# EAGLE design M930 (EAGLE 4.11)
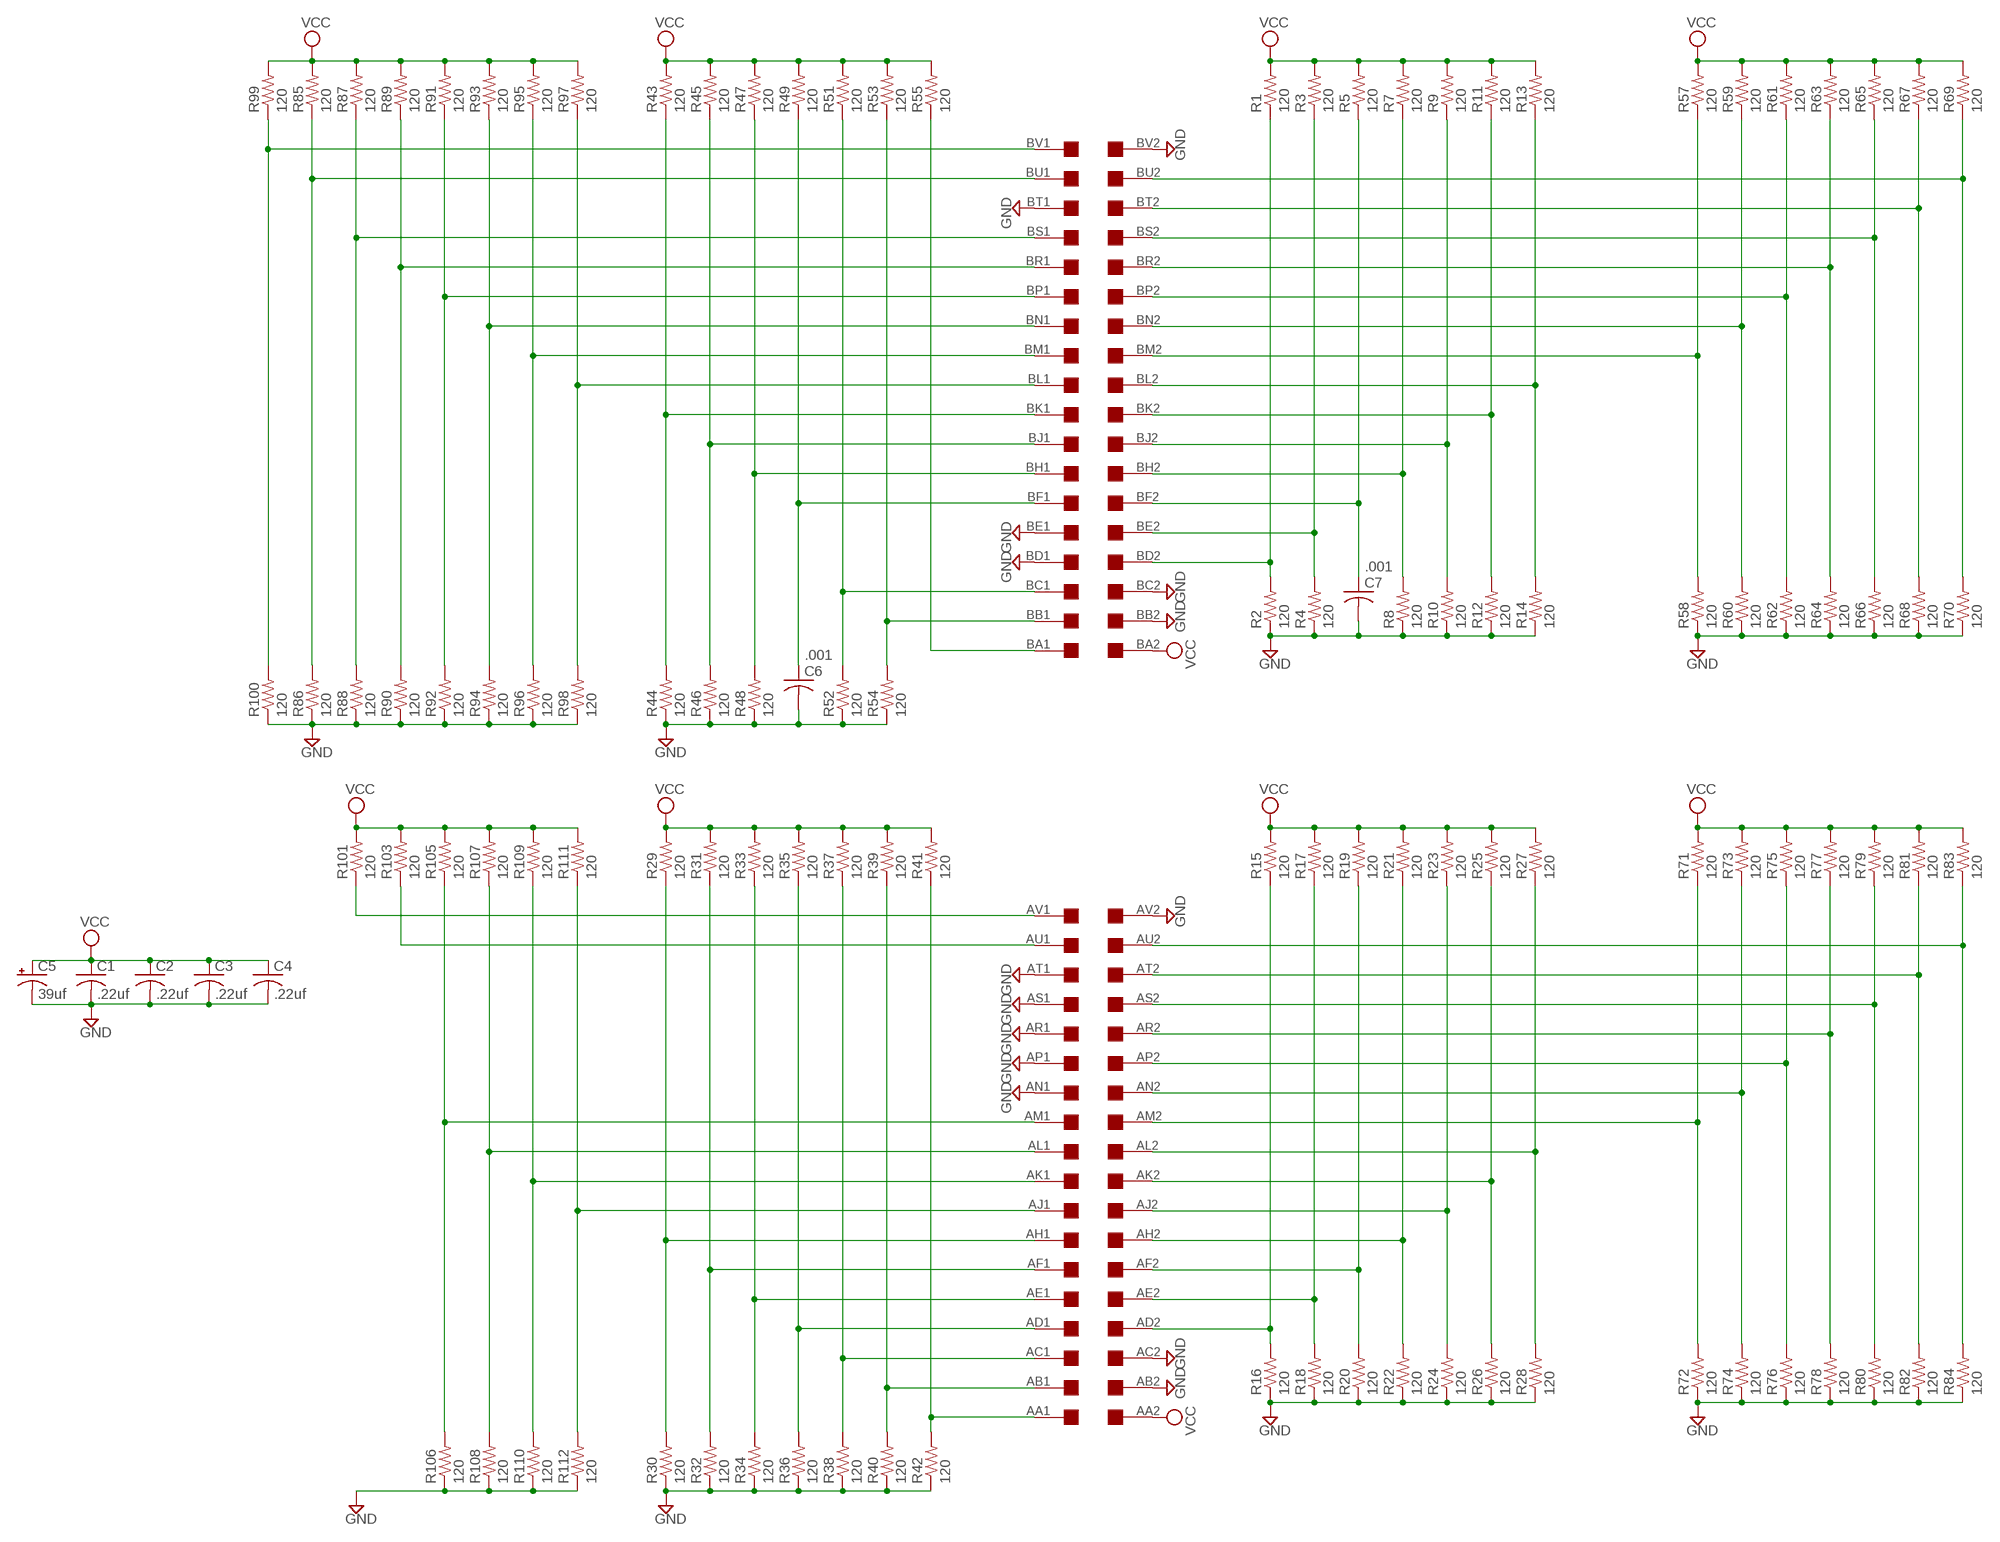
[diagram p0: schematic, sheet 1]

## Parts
C1  .22uf  C-US050-025X075  [C050-025X075]
C2  .22uf  C-US050-025X075  [C050-025X075]
C3  .22uf  C-US050-025X075  [C050-025X075]
C4  .22uf  C-US050-025X075  [C050-025X075]
C5  39uf  CPOL-USE15-5AXIAL  [E15-5]
C6  .001  C-US050-025X075  [C050-025X075]
C7  .001  C-US050-025X075  [C050-025X075]
R1  120  R-US_0207/10  [0207/10]
R2  120  R-US_0207/10  [0207/10]
R3  120  R-US_0207/10  [0207/10]
R4  120  R-US_0207/10  [0207/10]
R5  120  R-US_0207/10  [0207/10]
R7  120  R-US_0207/10  [0207/10]
R8  120  R-US_0207/10  [0207/10]
R9  120  R-US_0207/10  [0207/10]
R10  120  R-US_0207/10  [0207/10]
R11  120  R-US_0207/10  [0207/10]
R12  120  R-US_0207/10  [0207/10]
R13  120  R-US_0207/10  [0207/10]
R14  120  R-US_0207/10  [0207/10]
R15  120  R-US_0207/10  [0207/10]
R16  120  R-US_0207/10  [0207/10]
R17  120  R-US_0207/10  [0207/10]
R18  120  R-US_0207/10  [0207/10]
R19  120  R-US_0207/10  [0207/10]
R20  120  R-US_0207/10  [0207/10]
R21  120  R-US_0207/10  [0207/10]
R22  120  R-US_0207/10  [0207/10]
R23  120  R-US_0207/10  [0207/10]
R24  120  R-US_0207/10  [0207/10]
R25  120  R-US_0207/10  [0207/10]
R26  120  R-US_0207/10  [0207/10]
R27  120  R-US_0207/10  [0207/10]
R28  120  R-US_0207/10  [0207/10]
R29  120  R-US_0207/10  [0207/10]
R30  120  R-US_0207/10  [0207/10]
R31  120  R-US_0207/10  [0207/10]
R32  120  R-US_0207/10  [0207/10]
R33  120  R-US_0207/10  [0207/10]
R34  120  R-US_0207/10  [0207/10]
R35  120  R-US_0207/10  [0207/10]
R36  120  R-US_0207/10  [0207/10]
R37  120  R-US_0207/10  [0207/10]
R38  120  R-US_0207/10  [0207/10]
R39  120  R-US_0207/10  [0207/10]
R40  120  R-US_0207/10  [0207/10]
R41  120  R-US_0207/10  [0207/10]
R42  120  R-US_0207/10  [0207/10]
R43  120  R-US_0207/10  [0207/10]
R44  120  R-US_0207/10  [0207/10]
R45  120  R-US_0207/10  [0207/10]
R46  120  R-US_0207/10  [0207/10]
R47  120  R-US_0207/10  [0207/10]
R48  120  R-US_0207/10  [0207/10]
R49  120  R-US_0207/10  [0207/10]
R51  120  R-US_0207/10  [0207/10]
R52  120  R-US_0207/10  [0207/10]
R53  120  R-US_0207/10  [0207/10]
R54  120  R-US_0207/10  [0207/10]
R55  120  R-US_0207/10  [0207/10]
R57  120  R-US_0207/10  [0207/10]
R58  120  R-US_0207/10  [0207/10]
R59  120  R-US_0207/10  [0207/10]
R60  120  R-US_0207/10  [0207/10]
R61  120  R-US_0207/10  [0207/10]
R62  120  R-US_0207/10  [0207/10]
R63  120  R-US_0207/10  [0207/10]
R64  120  R-US_0207/10  [0207/10]
R65  120  R-US_0207/10  [0207/10]
R66  120  R-US_0207/10  [0207/10]
R67  120  R-US_0207/10  [0207/10]
R68  120  R-US_0207/10  [0207/10]
R69  120  R-US_0207/10  [0207/10]
R70  120  R-US_0207/10  [0207/10]
R71  120  R-US_0207/10  [0207/10]
R72  120  R-US_0207/10  [0207/10]
R73  120  R-US_0207/10  [0207/10]
R74  120  R-US_0207/10  [0207/10]
R75  120  R-US_0207/10  [0207/10]
R76  120  R-US_0207/10  [0207/10]
R77  120  R-US_0207/10  [0207/10]
R78  120  R-US_0207/10  [0207/10]
R79  120  R-US_0207/10  [0207/10]
R80  120  R-US_0207/10  [0207/10]
R81  120  R-US_0207/10  [0207/10]
R82  120  R-US_0207/10  [0207/10]
R83  120  R-US_0207/10  [0207/10]
R84  120  R-US_0207/10  [0207/10]
R85  120  R-US_0207/10  [0207/10]
R86  120  R-US_0207/10  [0207/10]
R87  120  R-US_0207/10  [0207/10]
R88  120  R-US_0207/10  [0207/10]
R89  120  R-US_0207/10  [0207/10]
R90  120  R-US_0207/10  [0207/10]
R91  120  R-US_0207/10  [0207/10]
R92  120  R-US_0207/10  [0207/10]
R93  120  R-US_0207/10  [0207/10]
R94  120  R-US_0207/10  [0207/10]
R95  120  R-US_0207/10  [0207/10]
R96  120  R-US_0207/10  [0207/10]
R97  120  R-US_0207/10  [0207/10]
R98  120  R-US_0207/10  [0207/10]
R99  120  R-US_0207/10  [0207/10]
R100  120  R-US_0207/10  [0207/10]
R101  120  R-US_0207/10  [0207/10]
R103  120  R-US_0207/10  [0207/10]
R105  120  R-US_0207/10  [0207/10]
R106  120  R-US_0207/10  [0207/10]
R107  120  R-US_0207/10  [0207/10]
R108  120  R-US_0207/10  [0207/10]
R109  120  R-US_0207/10  [0207/10]
R110  120  R-US_0207/10  [0207/10]
R111  120  R-US_0207/10  [0207/10]
R112  120  R-US_0207/10  [0207/10]
U$1  DOUBLE  [EDGE-CON4]

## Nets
AA1: R41.1 R42.2 U$1.AA1
AB1: R39.1 R40.2 U$1.AB1
AC1: R37.1 R38.2 U$1.AC1
AD1: R35.1 R36.2 U$1.AD1
AD2: R15.1 R16.2 U$1.AD2
AE1: R33.1 R34.2 U$1.AE1
AE2: R17.1 R18.2 U$1.AE2
AF1: R31.1 R32.2 U$1.AF1
AF2: R19.1 R20.2 U$1.AF2
AH1: R29.1 R30.2 U$1.AH1
AH2: R21.1 R22.2 U$1.AH2
AJ1: R111.1 R112.2 U$1.AJ1
AJ2: R23.1 R24.2 U$1.AJ2
AK1: R109.1 R110.2 U$1.AK1
AK2: R25.1 R26.2 U$1.AK2
AL1: R107.1 R108.2 U$1.AL1
AL2: R27.1 R28.2 U$1.AL2
AM1: R105.1 R106.2 U$1.AM1
AM2: R71.1 R72.2 U$1.AM2
AN2: R73.1 R74.2 U$1.AN2
AP2: R75.1 R76.2 U$1.AP2
AR2: R77.1 R78.2 U$1.AR2
AS2: R79.1 R80.2 U$1.AS2
AT2: R81.1 R82.2 U$1.AT2
AU1: R103.1 U$1.AU1
AU2: R83.1 R84.2 U$1.AU2
AV1: R101.1 U$1.AV1
BA1: R55.1 U$1.BA1
BB1: R53.1 R54.2 U$1.BB1
BC1: R51.1 R52.2 U$1.BC1
BD2: R1.1 R2.2 U$1.BD2
BE2: R3.1 R4.2 U$1.BE2
BF1: C6.1 R49.1 U$1.BF1
BF2: C7.1 R5.1 U$1.BF2
BH1: R47.1 R48.2 U$1.BH1
BH2: R7.1 R8.2 U$1.BH2
BJ1: R45.1 R46.2 U$1.BJ1
BJ2: R9.1 R10.2 U$1.BJ2
BK1: R43.1 R44.2 U$1.BK1
BK2: R11.1 R12.2 U$1.BK2
BL1: R97.1 R98.2 U$1.BL1
BL2: R13.1 R14.2 U$1.BL2
BM1: R95.1 R96.2 U$1.BM1
BM2: R57.1 R58.2 U$1.BM2
BN1: R93.1 R94.2 U$1.BN1
BN2: R59.1 R60.2 U$1.BN2
BP1: R91.1 R92.2 U$1.BP1
BP2: R61.1 R62.2 U$1.BP2
BR1: R89.1 R90.2 U$1.BR1
BR2: R63.1 R64.2 U$1.BR2
BS1: R87.1 R88.2 U$1.BS1
BS2: R65.1 R66.2 U$1.BS2
BT2: R67.1 R68.2 U$1.BT2
BU1: R85.1 R86.2 U$1.BU1
BU2: R69.1 R70.2 U$1.BU2
BV1: R99.1 R100.2 U$1.BV1
GND: C1.2 C2.2 C3.2 C4.2 C5.- C6.2 C7.2 R2.1 R4.1 R8.1 R10.1 R12.1 R14.1 R16.1 R18.1 R20.1 R22.1 R24.1 R26.1 R28.1 R30.1 R32.1 R34.1 R36.1 R38.1 R40.1 R42.1 R44.1 R46.1 R48.1 R52.1 R54.1 R58.1 R60.1 R62.1 R64.1 R66.1 R68.1 R70.1 R72.1 R74.1 R76.1 R78.1 R80.1 R82.1 R84.1 R86.1 R88.1 R90.1 R92.1 R94.1 R96.1 R98.1 R100.1 R106.1 R108.1 R110.1 R112.1 U$1.AB2 U$1.AC2 U$1.AN1 U$1.AP1 U$1.AR1 U$1.AS1 U$1.AT1 U$1.AV2 U$1.BB2 U$1.BC2 U$1.BD1 U$1.BE1 U$1.BT1 U$1.BV2
VCC: C1.1 C2.1 C3.1 C4.1 C5.+ R1.2 R3.2 R5.2 R7.2 R9.2 R11.2 R13.2 R15.2 R17.2 R19.2 R21.2 R23.2 R25.2 R27.2 R29.2 R31.2 R33.2 R35.2 R37.2 R39.2 R41.2 R43.2 R45.2 R47.2 R49.2 R51.2 R53.2 R55.2 R57.2 R59.2 R61.2 R63.2 R65.2 R67.2 R69.2 R71.2 R73.2 R75.2 R77.2 R79.2 R81.2 R83.2 R85.2 R87.2 R89.2 R91.2 R93.2 R95.2 R97.2 R99.2 R101.2 R103.2 R105.2 R107.2 R109.2 R111.2 U$1.AA2 U$1.BA2

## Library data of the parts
C1-C4 C6 C7 = rcl:C-US: CAPACITOR, American symbol
C5 = rcl:CPOL-US: POLARIZED CAPACITOR, American symbol
R1-R5 R7-R49 R51-R55 R57-R101 R103 R105-R112 = rcl:R-US_: RESISTOR, American symbol
U$1 = dec-con:DOUBLE: Double-Height DEC board

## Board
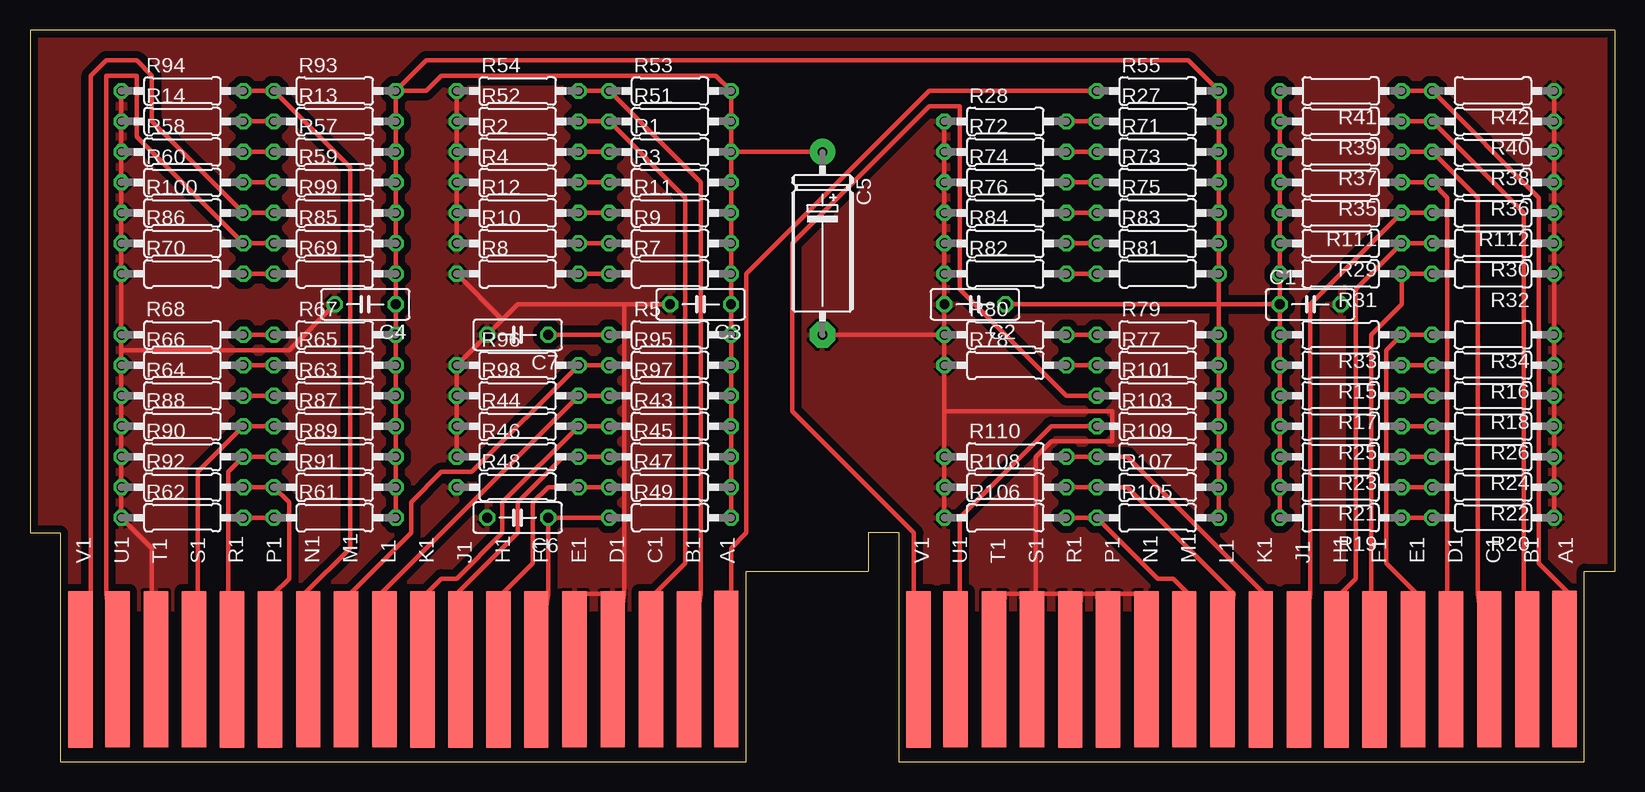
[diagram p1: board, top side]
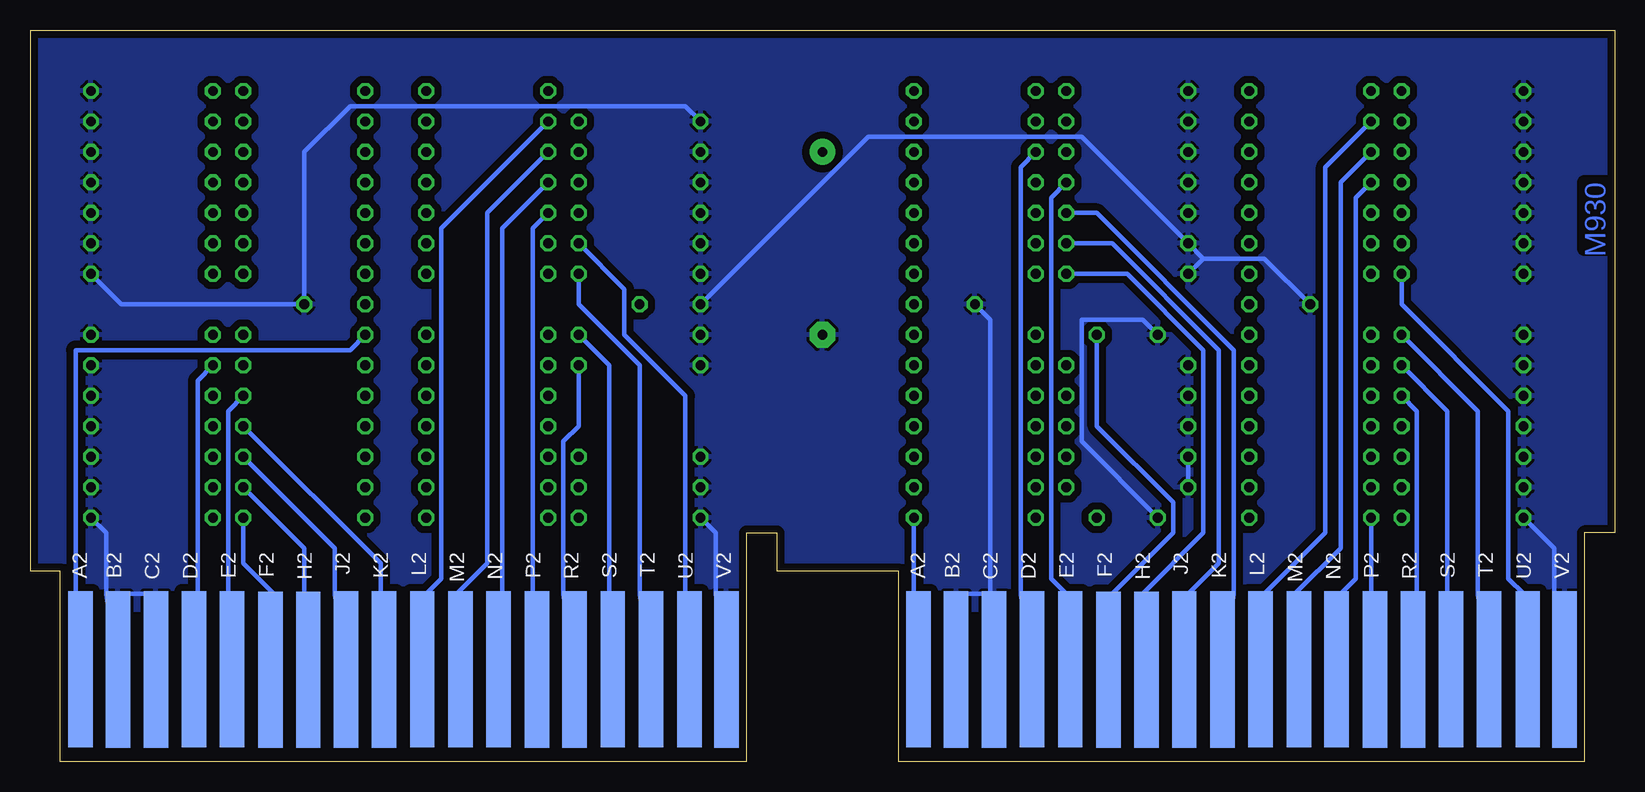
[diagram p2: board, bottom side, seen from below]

Size 132.08 x 60.96 mm. Coordinates in mm from the lower left corner, seen from the top.
Outline: 132.08,15.88 132.08,60.96 0,60.96 0,19.05
Copper layers (1*16): Top 0.035mm / dielectric 1.5mm / Bottom 0.035mm
Design rules "15mils": minimum track width 15mil, minimum drill 24mil, track to track 15mil, track to pad 10mil, pad to pad 10mil, via to via 10mil, smd to smd 10mil, copper to edge 25mil, drill to drill 10mil, minimum pad ring 10mil, minimum via ring 8mil, stop-mask expansion 0mil, vias tented up to drill 0mil, thermal gap 10mil

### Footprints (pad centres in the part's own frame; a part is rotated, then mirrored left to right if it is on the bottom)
C050-025X075 = drill 0.813 octagon: 1 -2.54,0; 2 2.54,0
E15-5 = drill 0.813 pad 2.159 round: + -7.62,0 | drill 0.813 pad 2.159 octagon: - 7.62,0
0207/10 = drill 0.813 octagon: 1 -5.08,0; 2 5.08,0
EDGE-CON4 = smd 13.017 x 2.032: AA1 7.709,4.207; AB1 7.684,7.312; AC1 7.684,10.474; AD1 7.684,13.665; AE1 7.693,16.84; AF1 7.668,20.041; AH1 7.668,23.19; AJ1 7.668,26.34; AK1 7.668,29.515; AL1 7.693,32.69; AM1 7.693,35.89; AN1 7.693,39.04; AP1 7.668,42.24; AR1 7.668,45.39; AS1 7.693,48.565; AT1 7.693,51.74; AU1 7.693,54.94; AV1 7.668,58.026; BA1 7.709,74.057; BB1 7.684,77.162; BC1 7.684,80.324; BD1 7.684,83.515; BE1 7.693,86.69; BF1 7.668,89.891; BH1 7.668,93.04; BJ1 7.668,96.19; BK1 7.668,99.365; BL1 7.693,102.54; BM1 7.693,105.74; BN1 7.693,108.89; BP1 7.668,112.09; BR1 7.668,115.24; BS1 7.693,118.415; BT1 7.693,121.59; BU1 7.693,124.79; BV1 7.668,127.876 | smd 13.017 x 2.032 bottom: AA2 7.69,4.207; AB2 7.668,7.328; AC2 7.668,10.49; AD2 7.693,13.665; AE2 7.693,16.84; AF2 7.642,20.041; AH2 7.642,23.19; AJ2 7.668,26.34; AK2 7.668,29.515; AL2 7.693,32.69; AM2 7.693,35.89; AN2 7.693,39.04; AP2 7.668,42.24; AR2 7.668,45.39; AS2 7.693,48.565; AT2 7.693,51.74; AU2 7.693,54.966; AV2 7.668,58.026; BA2 7.69,74.057; BB2 7.668,77.178; BC2 7.668,80.34; BD2 7.693,83.515; BE2 7.693,86.69; BF2 7.642,89.891; BH2 7.642,93.04; BJ2 7.668,96.19; BK2 7.668,99.365; BL2 7.693,102.54; BM2 7.693,105.74; BN2 7.693,108.89; BP2 7.668,112.09; BR2 7.668,115.24; BS2 7.693,118.415; BT2 7.693,121.59; BU2 7.693,124.816; BV2 7.668,127.876

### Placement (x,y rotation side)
C1  106.68,38.1 0 top
C2  78.74,38.1 180 top
C3  55.88,38.1 180 top
C4  27.94,38.1 180 top
C5  66.04,43.18 270 top
C6  40.64,20.32 180 top
C7  40.64,35.56 180 top
R1  53.34,50.8 0 top
R2  40.64,50.8 0 top
R3  53.34,48.26 0 top
R4  40.64,48.26 0 top
R5  53.34,35.56 0 top
R7  53.34,40.64 0 top
R8  40.64,40.64 0 top
R9  53.34,43.18 0 top
R10  40.64,43.18 0 top
R11  53.34,45.72 0 top
R12  40.64,45.72 0 top
R13  25.4,53.34 0 top
R14  12.7,53.34 0 top
R15  109.22,33.02 180 top
R16  121.92,33.02 180 top
R17  109.22,30.48 180 top
R18  121.92,30.48 180 top
R19  109.22,20.32 180 top
R20  121.92,20.32 180 top
R21  109.22,22.86 180 top
R22  121.92,22.86 180 top
R23  109.22,25.4 180 top
R24  121.92,25.4 180 top
R25  109.22,27.94 180 top
R26  121.92,27.94 180 top
R27  93.98,53.34 0 top
R28  81.28,53.34 0 top
R29  109.22,43.18 180 top
R30  121.92,43.18 180 top
R31  109.22,40.64 180 top
R32  121.92,40.64 180 top
R33  109.22,35.56 180 top
R34  121.92,35.56 180 top
R35  109.22,48.26 180 top
R36  121.92,48.26 180 top
R37  109.22,50.8 180 top
R38  121.92,50.8 180 top
R39  109.22,53.34 180 top
R40  121.92,53.34 180 top
R41  109.22,55.88 180 top
R42  121.92,55.88 180 top
R43  53.34,27.94 0 top
R44  40.64,27.94 0 top
R45  53.34,25.4 0 top
R46  40.64,25.4 0 top
R47  53.34,22.86 0 top
R48  40.64,22.86 0 top
R49  53.34,20.32 0 top
R51  53.34,53.34 0 top
R52  40.64,53.34 0 top
R53  53.34,55.88 0 top
R54  40.64,55.88 0 top
R55  93.98,55.88 0 top
R57  25.4,50.8 0 top
R58  12.7,50.8 0 top
R59  25.4,48.26 0 top
R60  12.7,48.26 0 top
R61  25.4,20.32 0 top
R62  12.7,20.32 0 top
R63  25.4,30.48 0 top
R64  12.7,30.48 0 top
R65  25.4,33.02 0 top
R66  12.7,33.02 0 top
R67  25.4,35.56 0 top
R68  12.7,35.56 0 top
R69  25.4,40.64 0 top
R70  12.7,40.64 0 top
R71  93.98,50.8 0 top
R72  81.28,50.8 0 top
R73  93.98,48.26 0 top
R74  81.28,48.26 0 top
R75  93.98,45.72 0 top
R76  81.28,45.72 0 top
R77  93.98,33.02 0 top
R78  81.28,33.02 0 top
R79  93.98,35.56 0 top
R80  81.28,35.56 0 top
R81  93.98,40.64 0 top
R82  81.28,40.64 0 top
R83  93.98,43.18 0 top
R84  81.28,43.18 0 top
R85  25.4,43.18 0 top
R86  12.7,43.18 0 top
R87  25.4,27.94 0 top
R88  12.7,27.94 0 top
R89  25.4,25.4 0 top
R90  12.7,25.4 0 top
R91  25.4,22.86 0 top
R92  12.7,22.86 0 top
R93  25.4,55.88 0 top
R94  12.7,55.88 0 top
R95  53.34,33.02 0 top
R96  40.64,33.02 0 top
R97  53.34,30.48 0 top
R98  40.64,30.48 0 top
R99  25.4,45.72 0 top
R100  12.7,45.72 0 top
R101  93.98,30.48 0 top
R103  93.98,27.94 0 top
R105  93.98,20.32 0 top
R106  81.28,20.32 0 top
R107  93.98,22.86 0 top
R108  81.28,22.86 0 top
R109  93.98,25.4 0 top
R110  81.28,25.4 0 top
R111  109.22,45.72 180 top
R112  121.92,45.72 180 top
U$1  132.08,0 90 top

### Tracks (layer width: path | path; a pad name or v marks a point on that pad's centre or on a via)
AA1
  Top 0.381: R41.1 R42.2 125.73,46.99 125.73,16.51 128.27,13.97 U$1.AA1
AB1
  Top 0.381: R39.1 R40.2 124.46,45.72 124.46,13.97 U$1.AB1
AC1
  Top 0.381: R37.1 R38.2 120.65,46.99 120.65,13.97 U$1.AC1
AD1
  Top 0.381: R35.1 R36.2 118.11,46.99 118.11,13.97 U$1.AD1
AD2
  Top 0.381: R16.2 R15.1
  Bottom 0.381: R16.2 118.11,31.75 118.11,13.97 U$1.AD2
AE1
  Top 0.381: R34.2 R33.1 113.03,34.29 113.03,16.51 115.57,13.97 U$1.AE1
AE2
  Top 0.381: R17.1 R18.2
  Bottom 0.381: R17.1 115.57,29.21 115.57,13.97 U$1.AE2
AF1
  Top 0.381: R32.2 R31.1 114.3,38.1 111.76,35.56 111.76,13.97 U$1.AF1
AF2
  Top 0.381: R19.1 R20.2
  Bottom 0.381: R19.1 114.3,16.51 111.76,13.97 U$1.AF2
AH1
  Top 0.381: R30.2 R29.1 110.49,39.37 110.49,15.24 109.22,13.97 U$1.AH1
AH2
  Top 0.381: R21.1 R22.2
  Bottom 0.381: R21.1 109.22,17.78 109.22,13.97 U$1.AH2
AJ1
  Top 0.381: R112.2 R111.1 106.68,38.1 106.68,13.97 U$1.AJ1
AJ2
  Top 0.381: R23.1 R24.2
  Bottom 0.381: R23.1 106.68,17.78 106.68,13.97 U$1.AJ2
AK1
  Top 0.381: R110.2 R109.1 91.44,25.4 102.87,13.97 U$1.AK1
AK2
  Top 0.381: R25.1 R26.2
  Bottom 0.381: R25.1 102.87,16.51 102.87,13.97 U$1.AK2
AL1
  Top 0.381: R108.2 R107.1 91.44,22.86 100.33,13.97 U$1.AL1
AL2
  Top 0.381: R27.1 R28.2
  Bottom 0.381: R27.1 97.79,44.45 97.79,15.24 99.06,13.97 U$1.AL2
AM1
  Top 0.381: R106.2 R105.1 93.98,15.24 95.25,15.24 96.52,13.97 U$1.AM1
AM2
  Top 0.381: R71.1 R72.2
  Bottom 0.381: R71.1 93.98,45.72 93.98,16.51 96.52,13.97 U$1.AM2
AN2
  Top 0.381: R73.1 R74.2
  Bottom 0.381: R73.1 92.71,44.45 92.71,13.97 U$1.AN2
AP2
  Top 0.381: R75.1 R76.2
  Bottom 0.381: R75.1 90.17,44.45 90.17,13.97 U$1.AP2
AR2
  Top 0.381: R78.2 R77.1
  Bottom 0.381: R78.2 86.36,27.94 87.63,26.67 87.63,13.97 U$1.AR2
AS2
  Top 0.381: R80.2 R79.1
  Bottom 0.381: R80.2 83.82,33.02 83.82,13.97 U$1.AS2
AT2
  Top 0.381: R82.2 R81.1
  Bottom 0.381: R82.2 86.36,38.1 81.28,33.02 81.28,13.97 U$1.AT2
AU1
  Top 0.381: R103.1 85.09,27.94 77.47,20.32 77.47,13.97 U$1.AU1
AU2
  Top 0.381: R84.2 R83.1
  Bottom 0.381: R84.2 82.55,39.37 82.55,35.56 77.47,30.48 77.47,13.97 U$1.AU2
AV1
  Top 0.381: R101.1 86.36,30.48 77.47,39.37 77.47,54.61 74.93,54.61 63.5,43.18 63.5,29.21 73.66,19.05 73.66,13.97 U$1.AV1
BA1
  Top 0.381: R55.1 74.93,55.88 59.69,40.64 59.69,19.05 58.42,17.78 58.42,13.97 U$1.BA1
BB1
  Top 0.381: R54.2 R53.1 55.88,48.26 55.88,13.97 U$1.BB1
BC1
  Top 0.381: R52.2 R51.1 54.61,46.99 54.61,16.51 52.07,13.97 U$1.BC1
BD2
  Top 0.381: R1.1 R2.2
  Bottom 0.381: R1.1 49.53,49.53 49.53,13.97 U$1.BD2
BE2
  Top 0.381: R4.2 R3.1
  Bottom 0.381: R4.2 46.99,46.99 46.99,15.24 45.72,13.97 U$1.BE2
BF1
  Top 0.381: R49.1 C6.1 43.18,13.97 U$1.BF1
BF2
  Top 0.381: C7.1 R5.1
  Bottom 0.381: C7.1 43.18,27.94 36.83,21.59 36.83,19.05 41.91,13.97 U$1.BF2
BH1
  Top 0.381: R47.1 R48.2 43.18,22.86 41.91,21.59 41.91,16.51 39.37,13.97 U$1.BH1
BH2
  Top 0.381: R8.2 R7.1
  Bottom 0.381: R8.2 40.64,40.64 34.29,34.29 34.29,19.05 39.37,13.97 U$1.BH2
BJ1
  Top 0.381: R45.1 R46.2 44.45,25.4 40.64,21.59 40.64,19.05 35.56,13.97 U$1.BJ1
BJ2
  Top 0.381: R10.2 R9.1
  Bottom 0.381: R10.2 41.91,43.18 33.02,34.29 33.02,16.51 35.56,13.97 U$1.BJ2
BK1
  Top 0.381: R43.1 R44.2 39.37,21.59 39.37,19.05 35.56,15.24 34.29,15.24 33.02,13.97 U$1.BK1
BK2
  Top 0.381: R12.2 R11.1
  Bottom 0.381: R12.2 43.18,45.72 31.75,34.29 31.75,13.97 U$1.BK2
BL1
  Top 0.381: R97.1 R98.2 29.21,13.97 U$1.BL1
BL2
  Top 0.381: R13.1 R14.2
  Bottom 0.381: R13.1 24.13,49.53 24.13,19.05 29.21,13.97 U$1.BL2
BM1
  Top 0.381: R95.1 R96.2 36.83,24.13 34.29,24.13 31.75,21.59 31.75,19.05 26.67,13.97 U$1.BM1
BM2
  Top 0.381: R57.1 R58.2
  Bottom 0.381: R57.1 22.86,48.26 22.86,17.78 26.67,13.97 U$1.BM2
BN1
  Top 0.381: R94.2 R93.1 26.67,49.53 26.67,17.78 22.86,13.97 U$1.BN1
BN2
  Top 0.381: R59.1 R60.2
  Bottom 0.381: R59.1 21.59,46.99 21.59,15.24 22.86,13.97 U$1.BN2
BP1
  Top 0.381: R92.2 R91.1 21.59,21.59 21.59,15.24 20.32,13.97 U$1.BP1
BP2
  Top 0.381: R61.1 R62.2
  Bottom 0.381: R61.1 20.32,13.97 U$1.BP2
BR1
  Top 0.381: R89.1 R90.2 16.51,24.13 16.51,13.97 U$1.BR1
BR2
  Top 0.381: R64.2 R63.1
  Bottom 0.381: R64.2 16.51,29.21 16.51,13.97 U$1.BR2
BS1
  Top 0.381: R87.1 R88.2 13.97,24.13 13.97,13.97 U$1.BS1
BS2
  Top 0.381: R66.2 R65.1
  Bottom 0.381: R66.2 13.97,29.21 13.97,13.97 U$1.BS2
BT2
  Top 0.381: R68.2 R67.1
  Bottom 0.381: R68.2 11.43,29.21 11.43,13.97 U$1.BT2
BU1
  Top 0.381: R85.1 R86.2 8.89,52.07 8.89,57.15 6.35,57.15 6.35,13.97 U$1.BU1
BU2
  Top 0.381: R70.2 R69.1
  Bottom 0.381: R70.2 17.78,38.1 8.89,29.21 8.89,15.24 7.62,13.97 U$1.BU2
BV1
  Top 0.381: R99.1 R100.2 10.16,53.34 10.16,57.15 8.89,58.42 6.35,58.42 5.08,57.15 5.08,13.97 U$1.BV1
GND
  Top 0.381: 7.62,34.29 R66.1 R64.1 R88.1 R90.1 R92.1 R62.1 10.16,17.78 10.16,13.97 U$1.BT1 | 7.62,34.29 R68.1 R70.1 R86.1 R100.1 R60.1 R58.1 R14.1 R94.1 | U$1.BE1 45.72,13.97 48.26,13.97 U$1.BD1 49.53,13.97 49.53,38.1 | R54.1 R52.1 R2.1 R4.1 R12.1 R10.1 | R46.1 R44.1 R98.1 R96.1 C7.2 39.37,36.83 | 49.53,38.1 40.64,38.1 39.37,36.83 | 49.53,38.1 C3.2 | R8.1 39.37,36.83 | 7.62,34.29 21.59,34.29 C4.2 | R20.1 R22.1 R24.1 R26.1 R18.1 R16.1 R34.1 R32.1 R30.1 R112.1 R36.1 R38.1 R40.1 R42.1 | U$1.AT1 81.28,13.97 82.55,13.97 U$1.AS1 | U$1.AN1 92.71,13.97 90.17,13.97 U$1.AP1 88.9,13.97 87.63,13.97 U$1.AR1 86.36,13.97 83.82,13.97 | 83.82,13.97 U$1.AS1 | R28.1 R72.1 R74.1 R76.1 R84.1 R82.1 C2.2 R80.1 | R106.1 R108.1 R110.1 76.2,29.21 | R80.1 R78.1 76.2,29.21 | R80.1 C5.- | 83.82,13.97 83.82,25.4 85.09,26.67 90.17,26.67 90.17,29.21 76.2,29.21 | 83.82,13.97 U$1.AS1
  Bottom 0.381: R62.1 5.08,17.78 5.08,13.97 U$1.BV2 | 52.07,13.97 54.61,13.97 U$1.BB2 | 52.07,13.97 U$1.BC2 | C4.2 29.21,41.91 34.29,41.91 | 34.29,41.91 R10.1 44.45,52.07 62.23,52.07 C2.2 | 34.29,41.91 R8.1 | R46.1 R48.1 | C6.2 44.45,26.67 44.45,36.83 39.37,36.83 C7.2 | 52.07,13.97 52.07,36.83 C3.2 | 52.07,13.97 U$1.BC2 | U$1.AC2 121.92,13.97 124.46,13.97 U$1.AB2 125.73,13.97 125.73,19.05 R20.1 | R32.1 124.46,38.1 C1.2 109.22,50.8 105.41,54.61 77.47,54.61 R28.1 | R106.1 74.93,19.05 74.93,13.97 U$1.AV2 | U$1.BC2 52.07,7.62
  pour Bottom (isolate 0.61): 0,60.96 132.08,60.96 132.08,12.7 0,12.7
  pour Top (isolate 0.61): 0,60.96 132.08,60.96 132.08,12.7 0,12.7
VCC
  Top 0.381: R93.2 R13.2 R57.2 R59.2 R99.2 R85.2 R69.2 C4.1 R67.2 R65.2 R63.2 R87.2 R89.2 R91.2 R61.2 | R1.2 R51.2 R53.2 57.15,57.15 34.29,57.15 33.02,55.88 R93.2 | R1.2 C5.+ | R49.2 R47.2 R45.2 R43.2 R97.2 R95.2 R5.2 C3.1 R7.2 R9.2 R11.2 R3.2 R1.2 | R19.2 R21.2 R23.2 R25.2 R17.2 R15.2 R33.2 C1.1 | R105.2 R107.2 R109.2 R103.2 R101.2 R77.2 R79.2 99.06,38.1 | R41.2 R39.2 R37.2 R35.2 R111.2 R29.2 R31.2 C1.1 | 99.06,38.1 C1.1 | 99.06,38.1 C2.1 | 99.06,38.1 R81.2 R83.2 R75.2 R73.2 R71.2 R27.2 R55.2 96.52,58.42 33.02,58.42 R93.2
  Bottom 0.381: R49.2 58.42,13.97 U$1.BA2 | R33.2 105.41,34.29 128.27,34.29 128.27,13.97 U$1.AA2

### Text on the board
Bottom: M930
tValues: M930 Unibus Terminator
